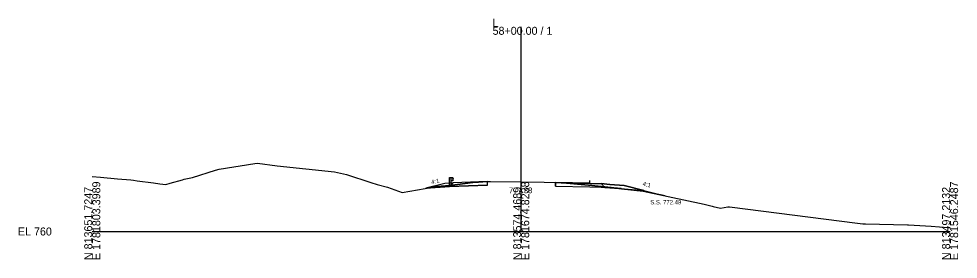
# Model space of a CAD drawing. Extents: x -26 to 7903, y -10 to 9573.
# Drawn here: x 1974.3 to 2302.8, y 8990.3 to 9074.4 of the extents above; entities that cross this region are included whole.
import ezdxf

# ---------------------------------------------------------------- set-up
doc = ezdxf.new("R2010")
doc.units = 0
for name, color, linetype in [('Exist Cross Section Cell', 7, 'Continuous'), ('Exist XS Center Line Elevation Label', 7, 'Continuous'), ('Exist XS Ground Line', 7, 'Continuous'), ('Prop XS Ditch Slope Text', 7, 'Continuous'), ('Prop XS Dump Level', 7, 'Continuous'), ('Prop XS Earthwork Shape', 7, 'Continuous'), ('Prop XS EOT Tick Mark', 7, 'Continuous'), ('Prop XS Finish Grade', 7, 'Continuous'), ('Prop XS Finish Grade Earthwork', 7, 'Continuous'), ('Prop XS Finish Grade Paved Shoulder', 7, 'Continuous'), ('Prop XS Finish Grade Pavement', 7, 'Continuous'), ('Prop XS Guardrail', 7, 'Continuous'), ('Prop XS Hydro Fill Slope Data', 7, 'Continuous'), ('Prop XS Pvmt Edge Slope', 7, 'Continuous'), ('Prop XS Side Slope Text', 7, 'Continuous'), ('Prop XS SS Elevation Text', 7, 'Continuous'), ('Prop XS Subgrade Earthwork', 7, 'Continuous'), ('Scratch_Level_3', 7, 'Continuous'), ('Scratch_Level_6', 7, 'Continuous')]:
    doc.layers.add(name, color=color, linetype=linetype)

msp = doc.modelspace()

# ---------------------------------------------------------------- linework, layer by layer
at = {"layer": 'Exist Cross Section Cell'}
for p, q in [((2150, 9000), (2150, 9071.58)), ((2000, 9000), (2150, 9000)), ((2150, 9000), (2300, 9000))]:
    msp.add_line(p, q, dxfattribs=at)
at = {"layer": 'Exist XS Ground Line'}
for p, q in [((2043.1, 9021.4), (2044.43, 9021.79)), ((2044.43, 9021.79), (2056.88, 9023.75)), ((2056.88, 9023.75), (2057.76, 9023.86)), ((2057.76, 9023.86), (2064.71, 9022.97)), ((2064.71, 9022.97), (2084.76, 9020.88)), ((2000, 9019.26), (2002.92, 9018.99)), ((2002.92, 9018.99), (2008.87, 9018.45)), ((2008.87, 9018.45), (2013.49, 9018.02)), ((2031.53, 9018.12), (2032.09, 9018.29)), ((2032.09, 9018.29), (2035.1, 9018.92)), ((2035.1, 9018.92), (2043.1, 9021.4)), ((2084.76, 9020.88), (2088.94, 9019.95)), ((2088.94, 9019.95), (2097.48, 9017.09)), ((2013.49, 9018.02), (2014.47, 9017.94)), ((2014.47, 9017.94), (2015.73, 9017.77)), ((2015.73, 9017.77), (2021.42, 9017.01)), ((2021.42, 9017.01), (2023.61, 9016.7)), ((2023.61, 9016.7), (2025.72, 9016.39)), ((2025.72, 9016.39), (2027.27, 9016.86)), ((2027.27, 9016.86), (2031.53, 9018.12)), ((2097.48, 9017.09), (2099.63, 9016.48)), ((2099.63, 9016.48), (2103.24, 9015.46)), ((2103.24, 9015.46), (2108.4, 9013.65)), ((2108.4, 9013.65), (2116.4, 9015.06)), ((2116.4, 9015.06), (2120.46, 9015.74)), ((2120.46, 9015.74), (2125.05, 9016.1)), ((2125.05, 9016.1), (2133.11, 9017.09)), ((2133.11, 9017.09), (2134.4, 9017.23)), ((2134.4, 9017.23), (2135.06, 9017.3)), ((2135.06, 9017.3), (2138.27, 9017.47)), ((2138.27, 9017.47), (2139.28, 9017.47)), ((2139.28, 9017.47), (2149.85, 9017.39)), ((2149.85, 9017.39), (2158.03, 9017.2)), ((2158.03, 9017.2), (2161.96, 9017.1)), ((2161.96, 9017.1), (2165.82, 9016.91)), ((2165.82, 9016.91), (2173.5, 9016.17)), ((2173.5, 9016.17), (2181.43, 9015.41)), ((2181.43, 9015.41), (2182.35, 9015.28)), ((2182.35, 9015.28), (2185.13, 9014.97)), ((2185.13, 9014.97), (2192.61, 9014.1)), ((2192.61, 9014.1), (2201.4, 9012.28)), ((2201.4, 9012.28), (2213.94, 9009.51)), ((2213.94, 9009.51), (2216.78, 9008.89)), ((2216.78, 9008.89), (2217.18, 9008.78)), ((2217.18, 9008.78), (2219.72, 9008.11)), ((2219.72, 9008.11), (2222.3, 9008.57)), ((2222.3, 9008.57), (2222.86, 9008.67)), ((2222.86, 9008.67), (2267.66, 9002.95)), ((2267.66, 9002.95), (2269.53, 9002.68)), ((2269.53, 9002.68), (2270.39, 9002.7)), ((2270.39, 9002.7), (2285.13, 9002.36)), ((2285.13, 9002.36), (2285.49, 9002.34)), ((2285.49, 9002.34), (2293.43, 9001.81)), ((2293.43, 9001.81), (2299.16, 9001.43)), ((2299.16, 9001.43), (2300, 9001.38))]:
    msp.add_line(p, q, dxfattribs=at)
at = {"layer": 'Prop XS Dump Level'}
for p, q in [((2161.97, 9017.15), (2174, 9016.9)), ((2174, 9016.9), (2161.97, 9017.15))]:
    msp.add_line(p, q, dxfattribs=at)
at = {"layer": 'Prop XS Earthwork Shape'}
for points in [[(2138.27, 9016.22), (2138.27, 9017.47), (2135.06, 9017.3), (2134.4, 9017.23), (2133.11, 9017.09), (2125.05, 9016.1), (2120.46, 9015.74), (2116.65, 9015.1), (2124.97, 9015.69)], [(2178, 9015.48), (2179.28, 9015.44), (2181, 9015.31), (2185.01, 9014.99), (2182.35, 9015.28), (2181.43, 9015.41), (2173.5, 9016.17), (2165.82, 9016.91), (2161.96, 9017.1), (2161.96, 9015.85), (2174, 9015.57)], [(2186, 9014.91), (2192.93, 9014.35), (2200.37, 9012.49), (2192.61, 9014.1), (2185.13, 9014.97), (2185.01, 9014.99)]]:
    msp.add_lwpolyline(points, close=True, dxfattribs=at)
at = {"layer": 'Prop XS EOT Tick Mark'}
msp.add_line((2174, 9016.82), (2174, 9017.82), dxfattribs=at)
at = {"layer": 'Prop XS Finish Grade'}
for p, q in [((2123.27, 9016.75), (2116.65, 9015.1)), ((2126.27, 9016.99), (2123.27, 9016.75)), ((2178, 9016.73), (2181, 9016.49)), ((2181, 9016.49), (2186, 9016.09)), ((2186, 9016.09), (2192.93, 9014.35))]:
    msp.add_line(p, q, dxfattribs=at)
at = {"layer": 'Prop XS Finish Grade Earthwork'}
msp.add_line((2192.93, 9014.35), (2200.37, 9012.49), dxfattribs=at)
at = {"layer": 'Prop XS Finish Grade Paved Shoulder'}
msp.add_line((2174, 9016.82), (2178, 9016.73), dxfattribs=at)
at = {"layer": 'Prop XS Finish Grade Pavement'}
for p, q in [((2138.27, 9017.47), (2126.27, 9016.99)), ((2161.96, 9017.1), (2174, 9016.82))]:
    msp.add_line(p, q, dxfattribs=at)
at = {"layer": 'Prop XS Guardrail'}
for p, q in [((2124.95, 9018.87), (2125.45, 9018.87)), ((2124.95, 9016.37), (2124.95, 9018.87)), ((2125.45, 9018.87), (2125.95, 9018.87)), ((2125.45, 9018.87), (2125.45, 9016.37)), ((2125.95, 9018.87), (2126.24, 9018.67)), ((2126.24, 9018.55), (2125.95, 9018.35)), ((2125.95, 9018.35), (2125.95, 9018.25)), ((2125.95, 9018.25), (2126.24, 9018.05)), ((2126.24, 9018.67), (2126.27, 9018.61)), ((2126.27, 9018.61), (2126.24, 9018.55)), ((2125.95, 9017.73), (2125.45, 9017.73)), ((2126.24, 9017.93), (2125.95, 9017.73)), ((2126.24, 9018.05), (2126.27, 9017.99)), ((2126.27, 9017.99), (2126.24, 9017.93))]:
    msp.add_line(p, q, dxfattribs=at)
at = {"layer": 'Prop XS Hydro Fill Slope Data'}
msp.add_line((2186, 9016.09), (2200.37, 9012.49), dxfattribs=at)
at = {"layer": 'Prop XS Pvmt Edge Slope'}
for p, q in [((2126.27, 9016.99), (2124.97, 9015.69)), ((2178, 9016.73), (2179.28, 9015.44))]:
    msp.add_line(p, q, dxfattribs=at)
at = {"layer": 'Prop XS Subgrade Earthwork'}
for p, q in [((2124.97, 9015.69), (2116.65, 9015.1)), ((2138.27, 9016.22), (2124.97, 9015.69)), ((2138.27, 9016.22), (2138.27, 9017.47)), ((2161.96, 9015.85), (2161.96, 9017.1)), ((2161.96, 9015.85), (2174, 9015.57)), ((2174, 9015.57), (2178, 9015.48)), ((2178, 9015.48), (2179.28, 9015.44)), ((2179.28, 9015.44), (2181, 9015.31)), ((2181, 9015.31), (2186, 9014.91)), ((2186, 9014.91), (2192.93, 9014.35))]:
    msp.add_line(p, q, dxfattribs=at)
at = {"layer": 'Scratch_Level_3'}
for p, q in [((2123.27, 9016.75), (2116.65, 9015.1)), ((2116.65, 9015.1), (2124.97, 9015.69)), ((2126.27, 9016.99), (2123.27, 9016.75)), ((2124.97, 9015.69), (2126.27, 9016.99)), ((2181, 9016.49), (2178, 9016.73)), ((2178, 9016.73), (2179.28, 9015.44)), ((2179.28, 9015.44), (2181, 9015.31)), ((2186, 9016.09), (2181, 9016.49)), ((2181, 9015.31), (2186, 9014.91)), ((2192.93, 9014.35), (2186, 9016.09)), ((2186, 9014.91), (2192.93, 9014.35))]:
    msp.add_line(p, q, dxfattribs=at)
at = {"layer": 'Scratch_Level_6'}
for points in [[(2138.27, 9016.22), (2138.27, 9017.47), (2135.06, 9017.3), (2134.4, 9017.23), (2133.11, 9017.09), (2125.05, 9016.1), (2120.46, 9015.74), (2116.65, 9015.1), (2124.97, 9015.69)], [(2181, 9015.31), (2185.01, 9014.99), (2182.35, 9015.28), (2181.43, 9015.41), (2173.5, 9016.17), (2165.82, 9016.91), (2161.96, 9017.1), (2161.96, 9015.85), (2174, 9015.57), (2178, 9015.48), (2179.28, 9015.44)]]:
    msp.add_lwpolyline(points, close=True, dxfattribs=at)

# ---------------------------------------------------------------- texts
at = {"layer": 'Exist Cross Section Cell'}
for s, p in [('L', (2140, 9071.58)), ('58+00.00 / 1', (2140, 9068.78)), ('EL 760', (1974, 8998.6))]:
    msp.add_text(s, height=2.8, dxfattribs=at).set_placement(p)
for s, p in [('N 813651.7247', (2000, 8990)), ('E 1781803.3989', (2002.8, 8990)), ('N 813574.4689', (2150, 8990)), ('E 1781674.8238', (2152.8, 8990)), ('N 813497.2132', (2300, 8990)), ('E 1781546.2487', (2302.8, 8990))]:
    msp.add_text(s, height=2.8, rotation=90, dxfattribs=at).set_placement(p)
at = {"layer": 'Exist XS Center Line Elevation Label'}
msp.add_text('777.38', height=2, dxfattribs=at).set_placement((2145.73, 9013.38))
at = {"layer": 'Prop XS Ditch Slope Text'}
msp.add_text('4:1', height=1.5, rotation=14.0362, dxfattribs=at).set_placement((2118.71, 9016.45))
at = {"layer": 'Prop XS Dump Level'}
for s, height, p in [('Eop', 0.3, (2161.96, 9016.8)), ('Case4', 0.04, (2186, 9016.05))]:
    msp.add_text(s, height=height, dxfattribs=at).set_placement(p)
at = {"layer": 'Prop XS Side Slope Text'}
msp.add_text('4:1', height=1.5, rotation=345.9638, dxfattribs=at).set_placement((2192.37, 9016.04))
at = {"layer": 'Prop XS SS Elevation Text'}
msp.add_text('S.S. 772.49', height=1.5, dxfattribs=at).set_placement((2195.15, 9009.49))

doc.saveas('drawing.dxf')
